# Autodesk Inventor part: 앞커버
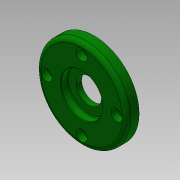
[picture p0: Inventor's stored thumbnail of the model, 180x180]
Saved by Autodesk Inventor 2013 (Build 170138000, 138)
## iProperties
Created: 2019-01
Part Number: 앞커버
Material: 알루미늄 6061
Document SubType Name: Modeling
Designer: mduedu
Density: 2.40731 g/cm^3
Mass: 58.9428 g
Surface Area: 91.8017 cm^2
Volume: 24.4849 cm^3
Author: mduedu
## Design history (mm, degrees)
sketch "스케치1"
  geometry: L1 (0, 0)-(9, 0); L2 (9, 0)-(9, 32); L3 (9, 32)-(0, 32); L4 (0, 32)-(0, 0); L5 (9, 0)-(12, 0); L6 (12, 0)-(12, 20); L7 (12, 20)-(9, 20); L8 (9, 20)-(9, 0)
  constraints: 16 end point, 4 parallel, 2 horizontal, 2 perpendicular
  dimensions: "d0" = 12 distance between parallel lines of L6 L4; "d2" = 64 diameter of L3 L1; "d3" = 40 diameter of L7 L5; "d4" = 3 distance between parallel lines of L6 L2
revolve "회전1" sketch "스케치1" stored, may be unused: angle "d5" = 90 deg
sketch "스케치2"
  geometry: L1 (0, -32)-(0, 32) reference; L2 (0, 32)-(9, 32) reference; L3 (9, 32)-(9, 20) reference; L4 (9, 20)-(12, 20) reference; L5 (12, 20)-(12, -20) reference; L6 (12, -20)-(9, -20) reference; L7 (9, -20)-(9, -32) reference; L8 (9, -32)-(0, -32) reference; L9 (0, 0)-(5.2, 0); L10 (5.2, 0)-(5.2, 15); L11 (5.2, 15)-(0, 15); L12 (0, 15)-(0, 0); L13 (5.2, 0)-(9, 0); L14 (9, 0)-(9, 9); L15 (9, 9)-(5.2, 9); L16 (5.2, 9)-(5.2, 0); L17 (9, 0)-(12, 0); L18 (12, 0)-(12, 15); L19 (12, 15)-(9, 15); L20 (9, 15)-(9, 0)
  constraints: 24 end point, 6 parallel, 3 horizontal, 3 perpendicular, 1 point on line
  dimensions: "d6" = 3 distance of L18.end L19.end; "d8" = 5.2 distance of L10.end L11.end; "d9" = 30 diameter of L11 L9; "d10" = 18 diameter of L15 L13; "d11" = 30 diameter of L19 L17
revolve "회전2" sketch "스케치2" stored, may be unused: angle "d12" = 90 deg
chamfer "모따기1" distance "d13" = 0.5; stored, may be unused: second distance "d14" = 2, angle "d15" = 30 deg
fillet "모깎기1" dims "d16" = 0.5
fillet "모깎기2" dims "d17" = 3
fillet "모깎기3" dims "d18" = 3
chamfer "모따기2" distance "d24" = 1; stored, may be unused: second distance "d25" = 2, angle "d26" = 45 deg
sketch "스케치3" dims "d19" = 50
  geometry: 6 further points
  constraints: 2 vertical alignment, 1 coincident, 7 other
  dimensions: "d22" = 360 deg dimension on point (0, 0) point (0, 25) (derived)
sketch "스케치4"
  geometry: 4 further points
  constraints: 4 other
hole "구멍1" sketch "스케치4" at (-25, 0), (0, -25), (25, 0), (0, 25) diameter "d27" = 4.5; stored, may be unused: countersink angle "d31" = 90 deg, drill point angle "d33" = 0 deg; dims "d28" = 6, "d29" = 8, "d30" = 4.6, "d32" = 8
node "솔리드1"
node "절단 모서리 투영1"
